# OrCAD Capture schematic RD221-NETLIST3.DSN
size A3
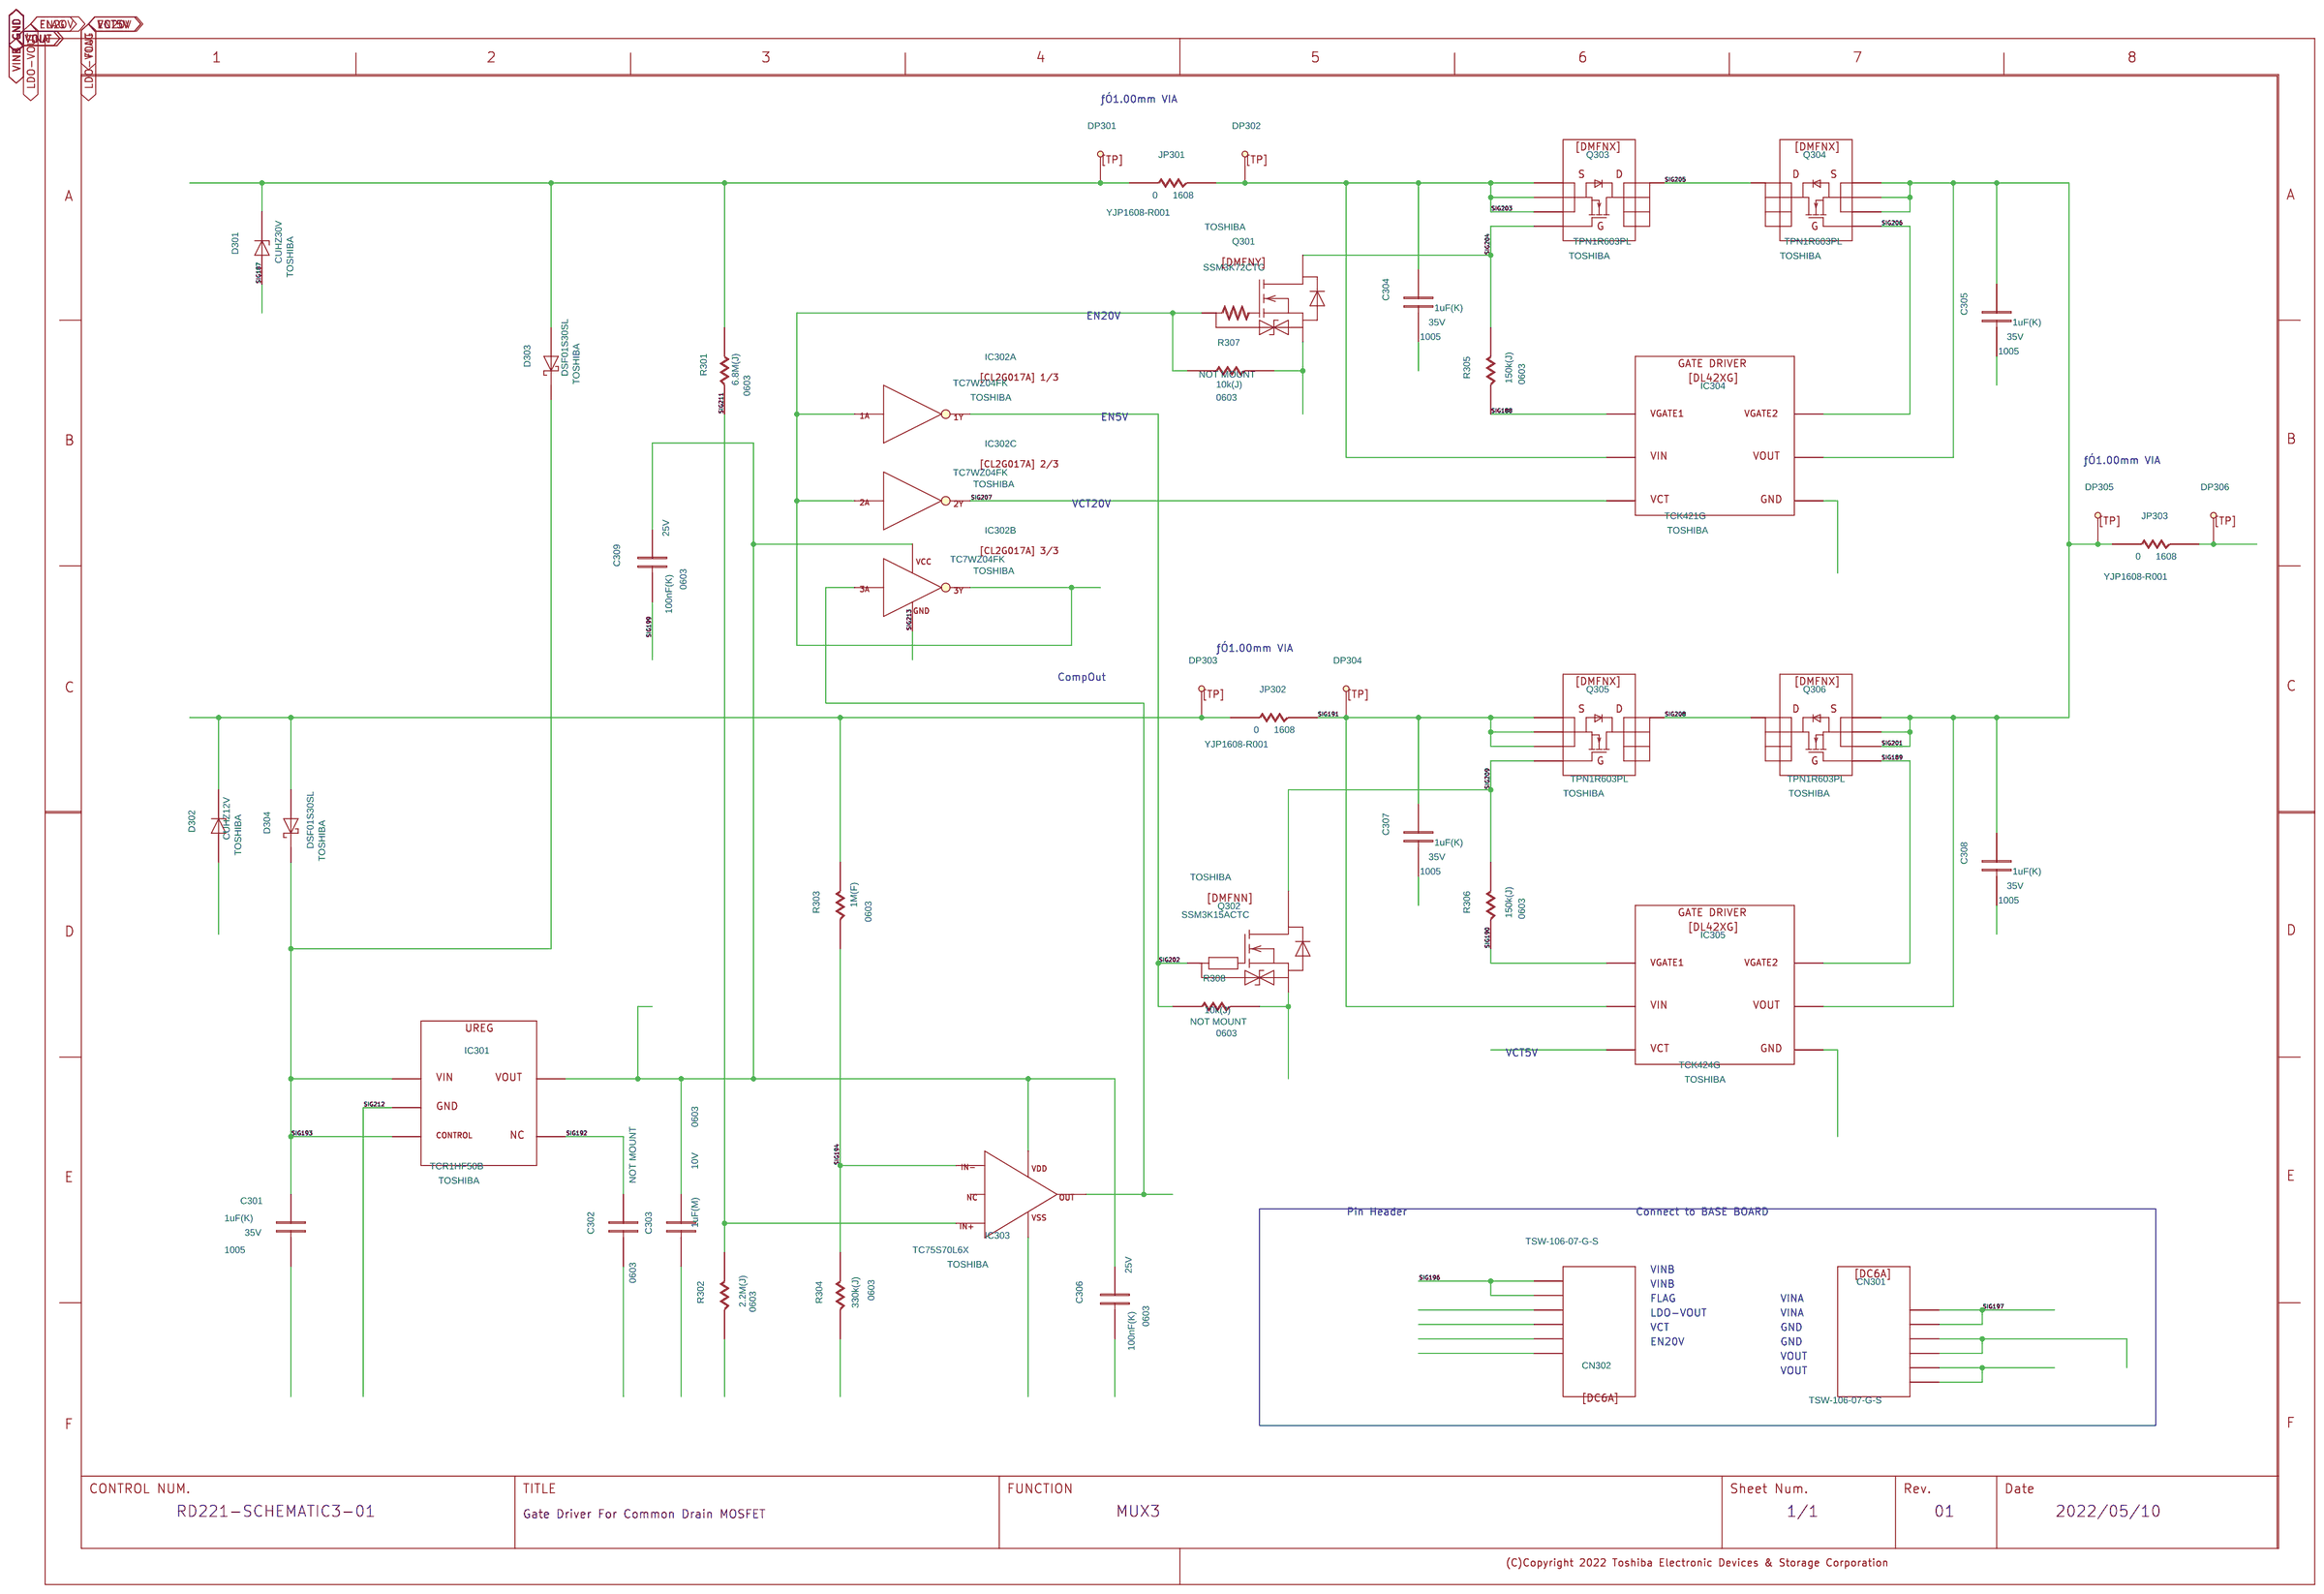
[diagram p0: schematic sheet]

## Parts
C301  DC
C302  DC
C303  DC
C304  DC
C305  DC
C306  DC
C307  DC
C308  DC
C309  DC
CN301  DC6A
CN302  DC6A
D301  DZD
D302  DZD
D303  DSBD
D304  DSBD
DP301  DTP
DP302  DTP
DP303  DTP
DP304  DTP
DP305  DTP
DP306  DTP
IC301  DL1HFXX
IC302  TC7WZ04FK_1  (sections A,B,C)
IC303  TC75S70L6X
IC304  DL42XG
IC305  DL42XG
JP301  DR
JP302  DR
JP303  DR
Q301  DMFNY
Q302  DMFNN
Q303  DMFNX
Q304  DMFNX
Q305  DMFNX
Q306  DMFNX
R301  DR
R302  DR
R303  DR
R304  DR
R305  DR
R306  DR
R307  DR
R308  DR
U?#1  WAKU_DEF100

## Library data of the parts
C301 C304 C305 C307 C308 = DC: ADSCNVFLAG: ON; ADSCOMPONENTNAME: C_1005; ADSMODELNAME: s_GRM155R6YA105KE11D; CAPACITANCETOLE: K; CDMASTERCADCELG: KC0005; COMP: DP0000016125; COMPONENTNAME: DP0000016125_package; FNLEADFREETHET1GT2GMCTH1: N_N_N; FUNCN: DP0000016125; GCOUNT: 1; ICX_PART_MODEL: CON_1u; MAXGCOUNT: 1; NOMINALCAPACITA: 1u; OUMECLASSIFICATION: ƒZƒ‰ƒ~ƒbƒNƒRƒ“ƒfƒ“ƒT; OUMEMAKER: MRT ºc»ì; OUMEMAKERKATAMEI: GRM155R6YA105KE11D; OUMEPARTTYPE: C; RATEDVOLTAGE: 35; SIZECODESMD: 1005; VAL1: 1uF(K); VAL2: 35V; VAL3: GRM155R6YA105KE11D
C302 = DC: ADSCNVFLAG: ON; ADSCOMPONENTNAME: C_0603; ADSMODELNAME: s_GRM033R61A105ME15D; CAPACITANCETOLE: M; CDMASTERCADCELG: KC0054; COMP: DP0010383000; COMPONENTNAME: DP0007093000_package; FNLEADFREETHET1GT2GMCTH1: N_N_N; FUNCN: DP0010383000; GCOUNT: 1; ICX_PART_MODEL: CON_1u; MAXGCOUNT: 1; NOMINALCAPACITA: 1u; NOTMOUNT: NOT MOUNT; OUMECLASSIFICATION: ƒZƒ‰ƒ~ƒbƒNƒRƒ“ƒfƒ“ƒT; OUMEMAKER: MRT ºc»ì; OUMEMAKERKATAMEI: GRM033R61A105ME15D; OUMEPARTTYPE: C; RATEDVOLTAGE: 10; SIZECODESMD: 0603; VAL1: 1uF(M); VAL2: 10V; VAL3: GRM033R61A105ME15D
C303 = DC: ADSCNVFLAG: ON; ADSCOMPONENTNAME: C_0603; ADSMODELNAME: s_GRM033R61A105ME15D; CAPACITANCETOLE: M; CDMASTERCADCELG: KC0054; COMP: DP0007093000; COMPONENTNAME: DP0007093000_package; FNLEADFREETHET1GT2GMCTH1: N_N_N; FUNCN: DP0007093000; GCOUNT: 1; ICX_PART_MODEL: CON_1u; MAXGCOUNT: 1; NOMINALCAPACITA: 1u; OUMECLASSIFICATION: ƒZƒ‰ƒ~ƒbƒNƒRƒ“ƒfƒ“ƒT; OUMEMAKER: MRT ºc»ì; OUMEMAKERKATAMEI: GRM033R61A105ME15D; OUMEPARTTYPE: C; RATEDVOLTAGE: 10; SIZECODESMD: 0603; VAL1: 1uF(M); VAL2: 10V; VAL3: GRM033R61A105ME15D
C306 C309 = DC: ADSCNVFLAG: ON; ADSCOMPONENTNAME: C_0603; ADSMODELNAME: s_GRM033R61E104KE14D; CAPACITANCETOLE: K; CDMASTERCADCELG: KC0054; COMP: DP0000015403; COMPONENTNAME: DP0000015403_package; FNLEADFREETHET1GT2GMCTH1: N_N_N; FUNCN: DP0000015403; GCOUNT: 1; ICX_PART_MODEL: CON_100n; MAXGCOUNT: 1; NOMINALCAPACITA: 100n; OUMECLASSIFICATION: ƒZƒ‰ƒ~ƒbƒNƒRƒ“ƒfƒ“ƒT; OUMEMAKER: MRT ºc»ì; OUMEMAKERKATAMEI: GRM033R61E104KE14D; OUMEPARTTYPE: C; RATEDVOLTAGE: 25; SIZECODESMD: 0603; VAL1: 100nF(K); VAL2: 25V; VAL3: GRM033R61E104KE14D
CN301 CN302 = DC6A: ADSCNVFLAG: ON; CDMASTERCADCELG: CU1200; COMP: DP0010563000; COMPONENTNAME: DP0010563000_package; CONTACTPITCH: 2.54; FNLEADFREETHET1GT2GMCTH1: N_N_N; FUNCN: DP0010563000; GCOUNT: 1; MAXGCOUNT: 1; NUMBEROFCONTACT: 6POS; OUMECLASSIFICATION: ƒvƒŠƒ“ƒg”Â’¼•t‚¯ƒRƒlƒNƒ^; OUMEMAKER: STC ƒTƒƒeƒbƒN; OUMEMAKERKATAMEI: TSW-106-07-G-S; OUMEPARTTYPE: CN; VAL3: TSW-106-07-G-S
D301 = DZD: ADSCNVFLAG: ON; ADSCOMPONENTNAME: D_DZD; ADSMODELNAME: s_CUHZ30V; CDMASTERCADCELG: MM0202; COMP: DP0010580000; COMPONENTNAME: DP0010557000_package; FNLEADFREETHET1GT2GMCTH1: N_N_N; FUNCN: DP0010580000; GCOUNT: 1; MAXGCOUNT: 1; MOUNTINGFORMSMD: SMD; OUMECLASSIFICATION: cFi[^èd³_CI[h; OUMEMAKER: TSB “ŒŽÅ; OUMEMAKERKATAMEI: CUHZ30V; OUMEPARTTYPE: D; USERCOMPTEXT3: TOSHIBA; VAL1: CUHZ30V; VAL3: CUHZ30V; ZENERVOLTAGEMAX: 32; ZENERVOLTAGEMIN: 28
D302 = DZD: ADSCNVFLAG: ON; ADSCOMPONENTNAME: D_DZD; ADSMODELNAME: s_CUHZ12V; CDMASTERCADCELG: MM0202; COMP: DP0010558000; COMPONENTNAME: DP0010584000_package; FNLEADFREETHET1GT2GMCTH1: N_N_N; FUNCN: DP0010558000; GCOUNT: 1; MAXGCOUNT: 1; MOUNTINGFORMSMD: SMD; OUMECLASSIFICATION: cFi[^èd³_CI[h; OUMEMAKER: TSB “ŒŽÅ; OUMEMAKERKATAMEI: CUHZ12V; OUMEPARTTYPE: D; USERCOMPTEXT3: TOSHIBA; VAL1: CUHZ12V; VAL3: CUHZ12V; ZENERVOLTAGEMAX: 12.6; ZENERVOLTAGEMIN: 11.4
D303 D304 = DSBD: ADSCNVFLAG: ON; ADSCOMPONENTNAME: D_DSBD; ADSMODELNAME: s_DSF01S30SL; CDMASTERCADCELG: KC1048; COMP: DP0010560000; COMPONENTNAME: DP0010560000_package; FNLEADFREETHET1GT2GMCTH1: N_N_N; FUNCN: DP0010560000; GCOUNT: 1; MAXAVERAGEFORWA: 100m; MAXGCOUNT: 1; MOUNTINGFORMSMD: SMD; OUMECLASSIFICATION: VbgL[oA_CI[h; OUMEMAKER: TSB “ŒŽÅ; OUMEMAKERKATAMEI: DSF01S30SL; OUMEPARTTYPE: D; USERCOMPTEXT3: TOSHIBA; VAL1: DSF01S30SL; VAL3: DSF01S30SL
DP301 = DTP: ADSCNVFLAG: ON; CDMASTERCADCELG: DP002X; COMP: DP9000817000; COMPONENTNAME: DP9000817000_package; FNLEADFREETHET1GT2GMCTH1: N_N_N; FUNCN: DP9000817000; GCOUNT: 1; KIND: PINƒsƒ“Ž®; MAXGCOUNT: 1; NOTMOUNT: NOT MOUNT; NUMBEROFCONTACT: 1; OUMEMAKER: ZZZ; OUMEMAKERKATAMEI: TPH0.9; OUMEPARTTYPE: TP; REUSEDCOMP: DP201; REUSEDFILE: RDxxx-SCHEMATIC3-01_REV_1_00_20211111; TERMINALSTYLE: 1H
DP302-DP306 = DTP: ADSCNVFLAG: ON; CDMASTERCADCELG: DP002X; COMP: DP9000817000; COMPONENTNAME: DP9000817000_package; FNLEADFREETHET1GT2GMCTH1: N_N_N; FUNCN: DP9000817000; GCOUNT: 1; KIND: PINƒsƒ“Ž®; MAXGCOUNT: 1; NOTMOUNT: NOT MOUNT; NUMBEROFCONTACT: 1; OUMEMAKER: ZZZ; OUMEMAKERKATAMEI: TPH0.9; OUMEPARTTYPE: TP; TERMINALSTYLE: 1H
IC301 = DL1HFXX: COMP: DP0008120000; FUNCN: DP0008120000; USERCOMPTEXT3: TOSHIBA; VAL1: TCR1HF50B; VAL3: TCR1HF50B
IC302 = TC7WZ04FK_1: COMP: DP0001429000; CaptureCellPackProp: TC7WZ04FK_1A; FUNCN: DP0001429000_1; USERCOMPTEXT3: TOSHIBA; VAL1: TC7WZ04FK; VAL3: TC7WZ04FK
IC303 = TC75S70L6X: COMP: DP0010561000; COMPONENTNAME: DP0010561000; FUNCN: DP0010561000; USERCOMPTEXT3: TOSHIBA
IC304 = DL42XG: ADSCNVFLAG: ON; CDMASTERCADCELG: BA1062; COMP: DP0010579000; COMPONENTNAME: DP0010555000_package; FNLEADFREETHET1GT2GMCTH1: N_N_N; FUNCN: DP0010579000; GCOUNT: 1; MAXGCOUNT: 1; MOUNTINGFORMSMD: SMD; OUMECLASSIFICATION: ‚»‚Ì‘¼; OUMEMAKER: TSB “ŒŽÅ; OUMEMAKERKATAMEI: TCK421G; OUMEPARTTYPE: IC; SAVEAREA0: 0,-2569,38100,25362; UPDATEDATE: 2021/11/09; UPDATETIME: 14:52:41; UPDATEUSER: t5459927; USERCOMPTEXT3: TOSHIBA; VAL1: TCK421G; VAL3: TCK421G
IC305 = DL42XG: ADSCNVFLAG: ON; CDMASTERCADCELG: BA1062; COMP: DP0010556000; COMPONENTNAME: DP0010583000_package; FNLEADFREETHET1GT2GMCTH1: N_N_N; FUNCN: DP0010556000; GCOUNT: 1; MAXGCOUNT: 1; MOUNTINGFORMSMD: SMD; OUMECLASSIFICATION: ‚»‚Ì‘¼; OUMEMAKER: TSB “ŒŽÅ; OUMEMAKERKATAMEI: TCK424G; OUMEPARTTYPE: IC; SAVEAREA0: -5715,0,43876,22860; UPDATEDATE: 2021/11/09; UPDATETIME: 13:49:24; UPDATEUSER: t5459927; USERCOMPTEXT3: TOSHIBA; VAL1: TCK424G; VAL3: TCK424G
JP301-JP303 = DR: ADSCNVFLAG: ON; ADSCOMPONENTNAME: R_1608; ADSMODELNAME: s_YJP1608-R001; CDMASTERCADCELG: KC0008; COMP: DP0001376000; COMPCOMMENT: 0; COMPONENTNAME: DP0001376000_package; FNLEADFREETHET1GT2GMCTH1: N_N_N; FUNCN: DP0001376000; GCOUNT: 1; ICX_PART_MODEL: RES_200u; MAXGCOUNT: 1; MOUNTINGFORMSMD: SMD; NOMINALRESISTAN: 200u; OUMECLASSIFICATION: ÅèïRí; OUMEMAKER: YDS ¡ldq¸H; OUMEMAKERKATAMEI: YJP1608-R001; OUMEPARTTYPE: R; POWERRATING: 30m; RESISTANCETOLER: X; SIZECODESMD: 1608; VAL1: 200u(X); VAL2: 30mW; VAL3: YJP1608-R001
Q301 = DMFNY: ADSCNVFLAG: ON; ADSCOMPONENTNAME: Q_DMFNY; ADSMODELNAME: s_SSM3K72CTC; CDMASTERCADCELG: LA1071; COMP: DP0010513000; COMPONENTNAME: DP0010564000_package; FNLEADFREETHET1GT2GMCTH1: N_N_N; FUNCN: DP0010513000; GCOUNT: 1; MAXDRAINCURRENT: 150m; MAXDSVOLTAGE: 60; MAXGCOUNT: 1; MOUNTINGFORMSMD: SMD; OUMECLASSIFICATION: m`llnr|eds; OUMEMAKER: TSB “ŒŽÅ; OUMEMAKERKATAMEI: SSM3K72CTC; OUMEPARTTYPE: Q; SAVEAREA0: -2026,0,24927,17780; UPDATEDATE: 2019/01/15; UPDATETIME: 15:53:55; UPDATEUSER: e1023210; USERCOMPTEXT3: TOSHIBA; VAL1: SSM3K72CTC; VAL3: SSM3K72CTC
Q302 = DMFNN: ADSCNVFLAG: ON; ADSCOMPONENTNAME: Q_DMFNN; ADSMODELNAME: s_SSM3K15ACTC; CDMASTERCADCELG: LA1071; COMP: DP0010513000; COMPONENTNAME: DP0010513000_package; DEVICE: RN4905; DEVICENAME: RN49A1FE(TE85L); FNLEADFREETHET1GT2GMCTH1: N_N_N; FUNCN: DP0010513000; FUNCTION: PNP&NPN_PCT; GCOUNT: 1; HETERO: RN4905_1,RN4905_2; LEVEL: STD; MAXDRAINCURRENT: 100m; MAXDSVOLTAGE: 30; MAXGCOUNT: 1; MOUNTINGFORMSMD: SMD; OUMECLASSIFICATION: m`llnr|eds; OUMEMAKER: TSB “ŒŽÅ; OUMEMAKERKATAMEI: SSM3K15ACTC; OUMEPARTTYPE: Q; P/D_NUM: TOSHIBA; PARTS: 1; PKG_TYPE: 2-2J1A; SAVEAREA0: -41191,-19664,61952,27881; UPDATEDATE: 2021/11/11; UPDATETIME: 08:00:04; UPDATEUSER: t5459927; USERCOMPTEXT3: TOSHIBA; VAL1: SSM3K15ACTC; VAL3: SSM3K15ACTC
Q303-Q306 = DMFNX: ADSCNVFLAG: ON; ADSCOMPONENTNAME: Q_DMFNX; ADSMODELNAME: s_TPN1R603PL; CDMASTERCADCELG: SN0061; COMP: DP0010582000; COMPONENTNAME: DP0010582000_package; FNLEADFREETHET1GT2GMCTH1: N_N_N; FUNCN: DP0010582000; GCOUNT: 1; MAXDRAINCURRENT: 80; MAXDSVOLTAGE: 30; MAXGCOUNT: 1; MOUNTINGFORMSMD: SMD; OUMECLASSIFICATION: m`llnr|eds; OUMEMAKER: TSB “ŒŽÅ; OUMEMAKERKATAMEI: TPN1R603PL; OUMEPARTTYPE: Q; USERCOMPTEXT3: TOSHIBA; VAL1: TPN1R603PL; VAL3: TPN1R603PL
R301 = DR: ADSCNVFLAG: ON; ADSCOMPONENTNAME: R_null; ADSMODELNAME: s_ERJ1GNJ685C; CDMASTERCADCELG: KC0054; COMP: DP0000151160; COMPONENTNAME: DP0000151164_package; FNLEADFREETHET1GT2GMCTH1: N_N_N; FUNCN: DP0000151160; GCOUNT: 1; ICX_PART_MODEL: RES_6.8M; MAXGCOUNT: 1; MOUNTINGFORMSMD: SMD; NOMINALRESISTAN: 6.8M; OUMECLASSIFICATION: ÅèïRí; OUMEMAKER: NAE pi\jbNGNgjbNfoCX; OUMEMAKERKATAMEI: ERJ1GNJ685C; OUMEPARTTYPE: R; POWERRATING: 50m; RESISTANCETOLER: J; SIZECODESMD: 0603; VAL1: 6.8M(J); VAL2: 50mW; VAL3: ERJ1GNJ685C
R302 = DR: ADSCNVFLAG: ON; ADSCOMPONENTNAME: R_null; ADSMODELNAME: s_ERJ1GNJ225C; CDMASTERCADCELG: KC0054; COMP: DP0000151148; COMPONENTNAME: DP0000151152_package; FNLEADFREETHET1GT2GMCTH1: N_N_N; FUNCN: DP0000151148; GCOUNT: 1; ICX_PART_MODEL: RES_2.2M; MAXGCOUNT: 1; MOUNTINGFORMSMD: SMD; NOMINALRESISTAN: 2.2M; OUMECLASSIFICATION: ÅèïRí; OUMEMAKER: NAE pi\jbNGNgjbNfoCX; OUMEMAKERKATAMEI: ERJ1GNJ225C; OUMEPARTTYPE: R; POWERRATING: 50m; RESISTANCETOLER: J; SIZECODESMD: 0603; VAL1: 2.2M(J); VAL2: 50mW; VAL3: ERJ1GNJ225C
R303 = DR: ADSCNVFLAG: ON; ADSCOMPONENTNAME: R_null; ADSMODELNAME: s_ERJ1GNF1004C; CDMASTERCADCELG: KC0054; COMP: DP0000152120; COMPONENTNAME: DP0000152120_package; FNLEADFREETHET1GT2GMCTH1: N_N_N; FUNCN: DP0000152120; GCOUNT: 1; ICX_PART_MODEL: RES_1M; MAXGCOUNT: 1; MOUNTINGFORMSMD: SMD; NOMINALRESISTAN: 1M; OUMECLASSIFICATION: ÅèïRí; OUMEMAKER: NAE pi\jbNGNgjbNfoCX; OUMEMAKERKATAMEI: ERJ1GNF1004C; OUMEPARTTYPE: R; POWERRATING: 50m; RESISTANCETOLER: F; SIZECODESMD: 0603; VAL1: 1M(F); VAL2: 50mW; VAL3: ERJ1GNF1004C
R304 = DR: ADSCNVFLAG: ON; ADSCOMPONENTNAME: R_null; ADSMODELNAME: s_ERJ1GNJ334C; CDMASTERCADCELG: KC0054; COMP: DP0000152120; COMPONENTNAME: DP0000151132_package; FNLEADFREETHET1GT2GMCTH1: N_N_N; FUNCN: DP0000152120; GCOUNT: 1; ICX_PART_MODEL: RES_330k; MAXGCOUNT: 1; MOUNTINGFORMSMD: SMD; NOMINALRESISTAN: 330k; OUMECLASSIFICATION: ÅèïRí; OUMEMAKER: NAE pi\jbNGNgjbNfoCX; OUMEMAKERKATAMEI: ERJ1GNJ334C; OUMEPARTTYPE: R; POWERRATING: 50m; RESISTANCETOLER: J; SIZECODESMD: 0603; VAL1: 330k(J); VAL2: 50mW; VAL3: ERJ1GNJ334C
R305 R306 = DR: ADSCNVFLAG: ON; ADSCOMPONENTNAME: R_null; ADSMODELNAME: s_RK73B1HTTC154J; CDMASTERCADCELG: KC0054; COMP: DP0000155124; COMPONENTNAME: DP0000155124_package; FNLEADFREETHET1GT2GMCTH1: N_N_N; FUNCN: DP0000155124; GCOUNT: 1; ICX_PART_MODEL: RES_150k; MAXGCOUNT: 1; MOUNTINGFORMSMD: SMD; NOMINALRESISTAN: 150k; OUMECLASSIFICATION: ÅèïRí; OUMEMAKER: KOA R[A; OUMEMAKERKATAMEI: RK73B1HTTC154J; OUMEPARTTYPE: R; POWERRATING: 50m; RESISTANCETOLER: J; SIZECODESMD: 0603; VAL1: 150k(J); VAL2: 50mW; VAL3: RK73B1HTTC154J
R307 R308 = DR: ADSCNVFLAG: ON; ADSCOMPONENTNAME: R_0603; ADSMODELNAME: s_RK73B1HTTCM103J; CDMASTERCADCELG: KC0054; COMP: DP0002867000; COMPONENTNAME: DP0002867000_package; FNLEADFREETHET1GT2GMCTH1: N_N_N; FUNCN: DP0002867000; GCOUNT: 1; ICX_PART_MODEL: RES_10k; MAXGCOUNT: 1; MOUNTINGFORMSMD: SMD; NOMINALRESISTAN: 10k; NOTMOUNT: NOT MOUNT; OUMECLASSIFICATION: ÅèïRí; OUMEMAKER: KOA R[A; OUMEMAKERKATAMEI: RK73B1HTTCM103J; OUMEPARTTYPE: R; POWERRATING: 50m; RESISTANCETOLER: J; SIZECODESMD: 0603; VAL1: 10k(J); VAL2: 50mW; VAL3: RK73B1HTTCM103J
U?#1 = WAKU_DEF100: DATE: 2022/05/10; DRAWINGNUMBER: RD221-SCHEMATIC3-01; FUNCTION: MUX3; REVISION: 01; SAVEAREA0: 148187,-66180,486823,89919; SAVECOUNT: 6; SHEETNUMBER: 1/1; TITLE: Gate Driver For Common Drain MOSFET; UPDATEDATE: 2022/05/17; UPDATETIME: 07:13:42

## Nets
GND: C301.2 C302.2 C303.2 C304.2 C305.2 C306.2 C307.2 C308.2 C309.2 CN301.3 CN301.4 D301.A D302.A IC301.2 IC302.4 IC303.2 IC304.B2 IC305.B2 Q301.S Q302.S R302.2 R304.2 R307.2 R308.2
VINA: CN301.1 CN301.2 D301.C D303.A DP301.1 JP301.1 R301.1
VINB: CN302.5 CN302.6 D302.C D304.A DP303.1 JP302.1 R303.1
EN20V: CN302.1 IC302.1 IC302.2 IC302.3 Q301.G R307.1
FLAG: CN302.4 IC302.6 IC303.1
LDO-VOUT: C303.1 C306.1 C309.1 CN302.3 IC301.5 IC302.8 IC303.6
SIG188: IC304.A1 R305.2
SIG189: IC305.B1 Q306.4
SIG190: IC305.A1 R306.2
SIG191: C307.1 DP304.1 IC305.A2 JP302.2 Q305.1 Q305.2 Q305.3
SIG192: C302.1 IC301.4
SIG193: C301.1 D303.C D304.C IC301.1 IC301.3
SIG194: IC303.4 R303.2 R304.1
SIG201: C305.1 C308.1 DP305.1 IC304.C1 IC305.C1 JP303.1 Q304.1 Q304.2 Q304.3 Q306.1 Q306.2 Q306.3
SIG202: IC302.7 Q302.G R308.1
SIG203: C304.1 DP302.1 IC304.A2 JP301.2 Q303.1 Q303.2 Q303.3
SIG204: Q301.D Q303.4 R305.1
SIG205: Q303.5 Q304.5
SIG206: IC304.B1 Q304.4
SIG207: IC302.5 IC304.C2
SIG208: Q305.5 Q306.5
SIG209: Q302.D Q305.4 R306.1
SIG211: IC303.3 R301.2 R302.1
VCT5V: CN302.2 IC305.C2
VOUT: CN301.5 CN301.6 DP306.1 JP303.2

Not connected (* = marked no-connect by the designer): IC303 5

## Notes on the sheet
- ƒÓ1.00mm VIA
- EN20V
- EN5V
- ƒÓ1.00mm VIA
- VCT20V
- ƒÓ1.00mm VIA
- CompOut
- VCT5V
- Pin Header
- Connect to BASE BOARD
- VINB
- VINB
- FLAG
- VINA
- LDO-VOUT
- VINA
- VCT
- GND
- EN20V
- GND
- VOUT
- VOUT
